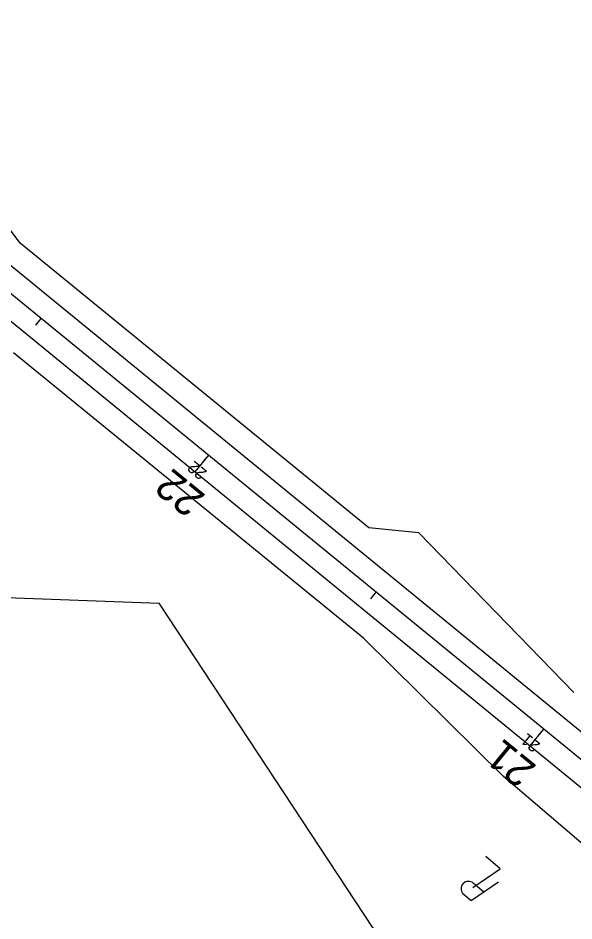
# Model space of a CAD drawing. Extents: x 2399886 to 2513208, y 556821 to 592417.
# Drawn here: x 2446201.4 to 2446329.9, y 557764.8 to 557973.5 of the extents above; entities that cross this region are included whole.
import ezdxf

# ---------------------------------------------------------------- set-up
doc = ezdxf.new("R2010")
doc.units = 0
for name, color, linetype in [('GM_X_Interchange_Ramps', 7, 'Continuous'), ('GM_X_Major_Lake', 7, 'Continuous'), ('GM_X_Major_River', 7, 'Continuous'), ('GM_X_Major_River_Text', 7, 'Continuous'), ('GM_X_Section', 7, 'Continuous'), ('SH_Data', 7, 'Continuous')]:
    doc.layers.add(name, color=color, linetype=linetype)

msp = doc.modelspace()

# ---------------------------------------------------------------- linework, layer by layer
at = {"layer": 'GM_X_Interchange_Ramps'}
for p, q in [((2446201.93, 557921.48), (2446180.1, 557950.48)), ((2446282.52, 557855.63), (2446201.93, 557921.48)), ((2446281.3, 557830.1), (2446200.39, 557896.07)), ((2446294.06, 557854.44), (2446282.52, 557855.63)), ((2446329.92, 557817.56), (2446294.06, 557854.44)), ((2446313.62, 557798.17), (2446281.3, 557830.1)), ((2446351.73, 557765.57), (2446313.62, 557798.17))]:
    msp.add_line(p, q, dxfattribs=at)
at = {"layer": 'GM_X_Major_Lake'}
for p, q in [((2446309.12, 557771.39), (2446306.66, 557773.5)), ((2446308.61, 557773.88), (2446308.61, 557773.88))]:
    msp.add_line(p, q, dxfattribs=at)
for points in [[(2446306.54, 557772.49), (2446312.85, 557776.82), (2446309.54, 557779.66)], [(2446312.5, 557773.73), (2446306.2, 557769.37), (2446304.24, 557771.05)]]:
    msp.add_lwpolyline(points, dxfattribs=at)
msp.add_arc((2446305.55, 557772.18), 1.72, 49.9078, 220.7649, dxfattribs=at)
at = {"layer": 'GM_X_Major_River'}
for p, q in [((2446555.11, 557619.22), (2446126.56, 557969.61)), ((2446245.44, 557872.41), (2446242.28, 557868.54)), ((2446322.86, 557809.11), (2446319.69, 557805.24))]:
    msp.add_line(p, q, dxfattribs=at)
at = {"layer": 'GM_X_Major_River_Text'}
for p in [(2446077.85, 557844.27), (2446904.5, 556820.84)]:
    msp.add_line(p, (2446234.03, 557838.18), dxfattribs=at)
at = {"layer": 'GM_X_Section'}
for p, q in [((2446558.5, 557622.9), (2446129.72, 557973.48)), ((2446551.72, 557615.53), (2446123.39, 557965.74))]:
    msp.add_line(p, q, dxfattribs=at)
at = {"layer": 'SH_Data'}
for p, q in [((2446555.11, 557619.22), (2446126.56, 557969.61)), ((2446206.73, 557904.06), (2446205.47, 557902.51)), ((2446245.44, 557872.41), (2446244.18, 557870.86)), ((2446284.15, 557840.76), (2446282.88, 557839.21)), ((2446322.86, 557809.11), (2446321.59, 557807.56))]:
    msp.add_line(p, q, dxfattribs=at)

# ---------------------------------------------------------------- texts
at = {"layer": 'GM_X_Major_River'}
for s, p in [('22', (2446245.03, 557863.06)), ('21', (2446321.54, 557800.5))]:
    msp.add_text(s, height=7, rotation=140.7295, dxfattribs=at).set_placement(p)
at = {"layer": 'SH_Data'}
for s, p in [('22', (2446245.28, 557868.67)), ('21', (2446322.33, 557805.67))]:
    msp.add_text(s, height=2.8, rotation=140.7295, dxfattribs=at).set_placement(p)

doc.saveas('drawing.dxf')
